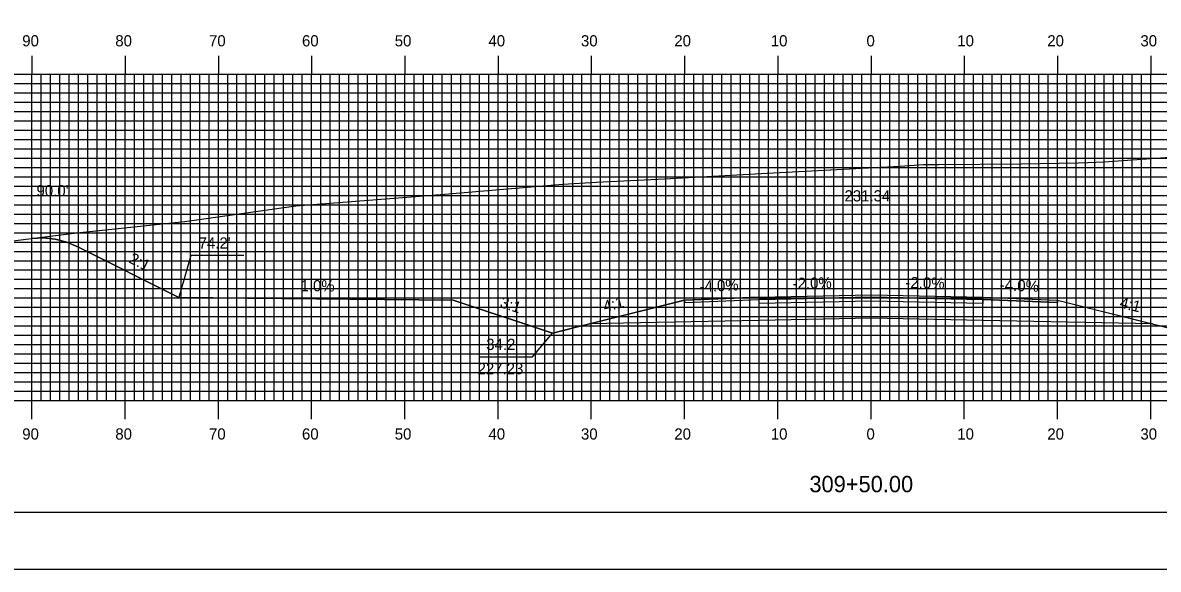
# Model space of a CAD drawing. Extents: x 1818063 to 1818407, y 442591 to 442811.
# Drawn here: x 1818138.1 to 1818259.9, y 442590.5 to 442649.2 of the extents above; entities that cross this region are included whole.
import ezdxf

# ---------------------------------------------------------------- set-up
doc = ezdxf.new("R2010")
doc.units = 0
for name, color, linetype in [('ANNOTATION', 7, 'Continuous'), ('BORDER', 7, 'Continuous'), ('D_Roadway_Centerline', 7, 'Continuous'), ('D_Roadway_Centerline_Text', 7, 'Continuous'), ('D_Roadway_Edge_Shoulder', 7, 'Continuous'), ('D_Roadway_Edge_TW', 7, 'Continuous'), ('D_Roadway_Pavement', 7, 'Continuous'), ('D_Roadway_SlopeLines', 7, 'Continuous'), ('D_Roadway_SubGrade', 7, 'Continuous'), ('D_Text_Standard', 7, 'Continuous'), ('H_V ANNOTATION', 7, 'Continuous'), ('MAJOR', 7, 'Continuous'), ('MINOR', 7, 'Continuous'), ('PLOT BOUNDARY', 7, 'Continuous'), ('S_Roadway_Centerline', 7, 'Continuous')]:
    doc.layers.add(name, color=color, linetype=linetype)

msp = doc.modelspace()

# ---------------------------------------------------------------- linework, layer by layer
at = {"layer": 'ANNOTATION'}
for points in [[(1818161.87, 442624.24), (1818156.18, 442624.24), (1818154.91, 442619.73)], [(1818187.13, 442613.36), (1818192.82, 442613.36), (1818194.95, 442615.9)]]:
    msp.add_lwpolyline(points, dxfattribs=at)
at = {"layer": 'BORDER'}
msp.add_lwpolyline([(1818079.53, 442596.67), (1818399.53, 442596.67), (1818399.53, 442806.67), (1818079.53, 442806.67)], close=True, dxfattribs=at)
at = {"layer": 'D_Roadway_Centerline'}
msp.add_lwpolyline([(1818139.13, 442626.06), (1818140.38, 442626.12), (1818141.63, 442625.99), (1818142.88, 442625.65), (1818144.13, 442625.13), (1818154.91, 442619.73), (1818184.32, 442619.44), (1818194.95, 442615.9), (1818198.95, 442616.9), (1818209.13, 442619.44), (1818217.13, 442619.76), (1818229.13, 442620), (1818241.13, 442619.76), (1818249.13, 442619.44), (1818259.3, 442616.9), (1818263.3, 442615.9), (1818273.93, 442619.44), (1818281.06, 442619.51), (1818314.13, 442636.04), (1818315.38, 442636.59), (1818316.63, 442637), (1818317.88, 442637.25), (1818319.13, 442637.35)], dxfattribs=at)
at = {"layer": 'D_Roadway_Edge_Shoulder'}
for points in [[(1818217.13, 442619.76), (1818209.13, 442619.44), (1818209.13, 442619.19), (1818217.13, 442619.51)], [(1818241.13, 442619.76), (1818249.13, 442619.44), (1818249.13, 442619.19), (1818241.13, 442619.51)]]:
    msp.add_lwpolyline(points, close=True, dxfattribs=at)
at = {"layer": 'D_Roadway_Edge_TW'}
msp.add_lwpolyline([(1818217.13, 442619.51), (1818217.13, 442619.76), (1818229.13, 442620), (1818241.13, 442619.76), (1818241.13, 442619.51), (1818229.13, 442619.75)], close=True, dxfattribs=at)
at = {"layer": 'D_Roadway_Pavement'}
msp.add_lwpolyline([(1818217.13, 442619.09), (1818217.13, 442619.51), (1818229.13, 442619.75), (1818241.13, 442619.51), (1818241.13, 442619.09), (1818229.13, 442619.33)], close=True, dxfattribs=at)
at = {"layer": 'D_Roadway_SlopeLines'}
for points in [[(1818184.32, 442619.44), (1818154.91, 442619.73), (1818144.13, 442625.13), (1818142.88, 442625.65), (1818141.63, 442625.99), (1818140.38, 442626.12), (1818139.13, 442626.06)], [(1818194.95, 442615.9), (1818184.32, 442619.44)], [(1818209.13, 442619.44), (1818194.95, 442615.9)], [(1818249.13, 442619.44), (1818263.3, 442615.9)]]:
    msp.add_lwpolyline(points, dxfattribs=at)
at = {"layer": 'D_Roadway_SubGrade'}
msp.add_lwpolyline([(1818217.13, 442617.26), (1818198.95, 442616.9), (1818209.13, 442619.44), (1818209.13, 442619.19), (1818217.13, 442619.51), (1818229.13, 442619.75), (1818241.13, 442619.51), (1818249.13, 442619.19), (1818249.13, 442619.44), (1818259.3, 442616.9), (1818241.13, 442617.26), (1818229.13, 442617.5)], close=True, dxfattribs=at)
at = {"layer": 'MAJOR'}
for p, q in [((1818139.13, 442645.67), (1818139.13, 442643.67)), ((1818149.13, 442645.67), (1818149.13, 442643.67)), ((1818159.13, 442645.67), (1818159.13, 442643.67)), ((1818169.13, 442645.67), (1818169.13, 442643.67)), ((1818179.13, 442645.67), (1818179.13, 442643.67)), ((1818189.13, 442645.67), (1818189.13, 442643.67)), ((1818199.13, 442645.67), (1818199.13, 442643.67)), ((1818209.13, 442645.67), (1818209.13, 442643.67)), ((1818219.13, 442645.67), (1818219.13, 442643.67)), ((1818229.13, 442645.67), (1818229.13, 442643.67)), ((1818239.13, 442645.67), (1818239.13, 442643.67)), ((1818249.13, 442645.67), (1818249.13, 442643.67)), ((1818259.13, 442645.67), (1818259.13, 442643.67)), ((1818089.13, 442643.67), (1818369.13, 442643.67)), ((1818089.13, 442643.67), (1818369.13, 442643.67)), ((1818139.13, 442608.67), (1818139.13, 442643.67)), ((1818149.13, 442608.67), (1818149.13, 442643.67)), ((1818159.13, 442608.67), (1818159.13, 442643.67)), ((1818169.13, 442608.67), (1818169.13, 442643.67)), ((1818179.13, 442608.67), (1818179.13, 442643.67)), ((1818189.13, 442608.67), (1818189.13, 442643.67)), ((1818199.13, 442608.67), (1818199.13, 442643.67)), ((1818209.13, 442608.67), (1818209.13, 442643.67)), ((1818219.13, 442608.67), (1818219.13, 442643.67)), ((1818229.13, 442608.67), (1818229.13, 442643.67)), ((1818239.13, 442608.67), (1818239.13, 442643.67)), ((1818249.13, 442608.67), (1818249.13, 442643.67)), ((1818259.13, 442608.67), (1818259.13, 442643.67)), ((1818089.13, 442638.67), (1818369.13, 442638.67)), ((1818089.13, 442633.67), (1818369.13, 442633.67)), ((1818089.13, 442628.67), (1818369.13, 442628.67)), ((1818089.13, 442623.67), (1818369.13, 442623.67)), ((1818089.13, 442618.67), (1818369.13, 442618.67)), ((1818089.13, 442613.67), (1818369.13, 442613.67)), ((1818089.13, 442608.67), (1818369.13, 442608.67)), ((1818089.13, 442608.67), (1818369.13, 442608.67)), ((1818139.13, 442606.66), (1818139.13, 442608.67)), ((1818149.13, 442606.66), (1818149.13, 442608.67)), ((1818159.13, 442606.66), (1818159.13, 442608.67)), ((1818169.13, 442606.66), (1818169.13, 442608.67)), ((1818179.13, 442606.66), (1818179.13, 442608.67)), ((1818189.13, 442606.66), (1818189.13, 442608.67)), ((1818199.13, 442606.66), (1818199.13, 442608.67)), ((1818209.13, 442606.66), (1818209.13, 442608.67)), ((1818219.13, 442606.66), (1818219.13, 442608.67)), ((1818229.13, 442606.66), (1818229.13, 442608.67)), ((1818239.13, 442606.66), (1818239.13, 442608.67)), ((1818249.13, 442606.66), (1818249.13, 442608.67)), ((1818259.13, 442606.66), (1818259.13, 442608.67))]:
    msp.add_line(p, q, dxfattribs=at)
at = {"layer": 'MINOR'}
for p, q in [((1818140.13, 442608.67), (1818140.13, 442643.67)), ((1818141.13, 442608.67), (1818141.13, 442643.67)), ((1818142.13, 442608.67), (1818142.13, 442643.67)), ((1818143.13, 442608.67), (1818143.13, 442643.67)), ((1818144.13, 442608.67), (1818144.13, 442643.67)), ((1818145.13, 442608.67), (1818145.13, 442643.67)), ((1818146.13, 442608.67), (1818146.13, 442643.67)), ((1818147.13, 442608.67), (1818147.13, 442643.67)), ((1818148.13, 442608.67), (1818148.13, 442643.67)), ((1818150.13, 442608.67), (1818150.13, 442643.67)), ((1818151.13, 442608.67), (1818151.13, 442643.67)), ((1818152.13, 442608.67), (1818152.13, 442643.67)), ((1818153.13, 442608.67), (1818153.13, 442643.67)), ((1818154.13, 442608.67), (1818154.13, 442643.67)), ((1818155.13, 442608.67), (1818155.13, 442643.67)), ((1818156.13, 442608.67), (1818156.13, 442643.67)), ((1818157.13, 442608.67), (1818157.13, 442643.67)), ((1818158.13, 442608.67), (1818158.13, 442643.67)), ((1818160.13, 442608.67), (1818160.13, 442643.67)), ((1818161.13, 442608.67), (1818161.13, 442643.67)), ((1818162.13, 442608.67), (1818162.13, 442643.67)), ((1818163.13, 442608.67), (1818163.13, 442643.67)), ((1818164.13, 442608.67), (1818164.13, 442643.67)), ((1818165.13, 442608.67), (1818165.13, 442643.67)), ((1818166.13, 442608.67), (1818166.13, 442643.67)), ((1818167.13, 442608.67), (1818167.13, 442643.67)), ((1818168.13, 442608.67), (1818168.13, 442643.67)), ((1818170.13, 442608.67), (1818170.13, 442643.67)), ((1818171.13, 442608.67), (1818171.13, 442643.67)), ((1818172.13, 442608.67), (1818172.13, 442643.67)), ((1818173.13, 442608.67), (1818173.13, 442643.67)), ((1818174.13, 442608.67), (1818174.13, 442643.67)), ((1818175.13, 442608.67), (1818175.13, 442643.67)), ((1818176.13, 442608.67), (1818176.13, 442643.67)), ((1818177.13, 442608.67), (1818177.13, 442643.67)), ((1818178.13, 442608.67), (1818178.13, 442643.67)), ((1818180.13, 442608.67), (1818180.13, 442643.67)), ((1818181.13, 442608.67), (1818181.13, 442643.67)), ((1818182.13, 442608.67), (1818182.13, 442643.67)), ((1818183.13, 442608.67), (1818183.13, 442643.67)), ((1818184.13, 442608.67), (1818184.13, 442643.67)), ((1818185.13, 442608.67), (1818185.13, 442643.67)), ((1818186.13, 442608.67), (1818186.13, 442643.67)), ((1818187.13, 442608.67), (1818187.13, 442643.67)), ((1818188.13, 442608.67), (1818188.13, 442643.67)), ((1818190.13, 442608.67), (1818190.13, 442643.67)), ((1818191.13, 442608.67), (1818191.13, 442643.67)), ((1818192.13, 442608.67), (1818192.13, 442643.67)), ((1818193.13, 442608.67), (1818193.13, 442643.67)), ((1818194.13, 442608.67), (1818194.13, 442643.67)), ((1818195.13, 442608.67), (1818195.13, 442643.67)), ((1818196.13, 442608.67), (1818196.13, 442643.67)), ((1818197.13, 442608.67), (1818197.13, 442643.67)), ((1818198.13, 442608.67), (1818198.13, 442643.67)), ((1818200.13, 442608.67), (1818200.13, 442643.67)), ((1818201.13, 442608.67), (1818201.13, 442643.67)), ((1818202.13, 442608.67), (1818202.13, 442643.67)), ((1818203.13, 442608.67), (1818203.13, 442643.67)), ((1818204.13, 442608.67), (1818204.13, 442643.67)), ((1818205.13, 442608.67), (1818205.13, 442643.67)), ((1818206.13, 442608.67), (1818206.13, 442643.67)), ((1818207.13, 442608.67), (1818207.13, 442643.67)), ((1818208.13, 442608.67), (1818208.13, 442643.67)), ((1818210.13, 442608.67), (1818210.13, 442643.67)), ((1818211.13, 442608.67), (1818211.13, 442643.67)), ((1818212.13, 442608.67), (1818212.13, 442643.67)), ((1818213.13, 442608.67), (1818213.13, 442643.67)), ((1818214.13, 442608.67), (1818214.13, 442643.67)), ((1818215.13, 442608.67), (1818215.13, 442643.67)), ((1818216.13, 442608.67), (1818216.13, 442643.67)), ((1818217.13, 442608.67), (1818217.13, 442643.67)), ((1818218.13, 442608.67), (1818218.13, 442643.67)), ((1818220.13, 442608.67), (1818220.13, 442643.67)), ((1818221.13, 442608.67), (1818221.13, 442643.67)), ((1818222.13, 442608.67), (1818222.13, 442643.67)), ((1818223.13, 442608.67), (1818223.13, 442643.67)), ((1818224.13, 442608.67), (1818224.13, 442643.67)), ((1818225.13, 442608.67), (1818225.13, 442643.67)), ((1818226.13, 442608.67), (1818226.13, 442643.67)), ((1818227.13, 442608.67), (1818227.13, 442643.67)), ((1818228.13, 442608.67), (1818228.13, 442643.67)), ((1818230.13, 442608.67), (1818230.13, 442643.67)), ((1818231.13, 442608.67), (1818231.13, 442643.67)), ((1818232.13, 442608.67), (1818232.13, 442643.67)), ((1818233.13, 442608.67), (1818233.13, 442643.67)), ((1818234.13, 442608.67), (1818234.13, 442643.67)), ((1818235.13, 442608.67), (1818235.13, 442643.67)), ((1818236.13, 442608.67), (1818236.13, 442643.67)), ((1818237.13, 442608.67), (1818237.13, 442643.67)), ((1818238.13, 442608.67), (1818238.13, 442643.67)), ((1818240.13, 442608.67), (1818240.13, 442643.67)), ((1818241.13, 442608.67), (1818241.13, 442643.67)), ((1818242.13, 442608.67), (1818242.13, 442643.67)), ((1818243.13, 442608.67), (1818243.13, 442643.67)), ((1818244.13, 442608.67), (1818244.13, 442643.67)), ((1818245.13, 442608.67), (1818245.13, 442643.67)), ((1818246.13, 442608.67), (1818246.13, 442643.67)), ((1818247.13, 442608.67), (1818247.13, 442643.67)), ((1818248.13, 442608.67), (1818248.13, 442643.67)), ((1818250.13, 442608.67), (1818250.13, 442643.67)), ((1818251.13, 442608.67), (1818251.13, 442643.67)), ((1818252.13, 442608.67), (1818252.13, 442643.67)), ((1818253.13, 442608.67), (1818253.13, 442643.67)), ((1818254.13, 442608.67), (1818254.13, 442643.67)), ((1818255.13, 442608.67), (1818255.13, 442643.67)), ((1818256.13, 442608.67), (1818256.13, 442643.67)), ((1818257.13, 442608.67), (1818257.13, 442643.67)), ((1818258.13, 442608.67), (1818258.13, 442643.67)), ((1818089.13, 442642.67), (1818369.13, 442642.67)), ((1818089.13, 442641.67), (1818369.13, 442641.67)), ((1818089.13, 442640.67), (1818369.13, 442640.67)), ((1818089.13, 442639.67), (1818369.13, 442639.67)), ((1818089.13, 442637.67), (1818369.13, 442637.67)), ((1818089.13, 442636.67), (1818369.13, 442636.67)), ((1818089.13, 442635.67), (1818369.13, 442635.67)), ((1818089.13, 442634.67), (1818369.13, 442634.67)), ((1818089.13, 442632.67), (1818369.13, 442632.67)), ((1818089.13, 442631.67), (1818369.13, 442631.67)), ((1818089.13, 442630.67), (1818369.13, 442630.67)), ((1818089.13, 442629.67), (1818369.13, 442629.67)), ((1818089.13, 442627.67), (1818369.13, 442627.67)), ((1818089.13, 442626.67), (1818369.13, 442626.67)), ((1818089.13, 442625.67), (1818369.13, 442625.67)), ((1818089.13, 442624.67), (1818369.13, 442624.67)), ((1818089.13, 442622.67), (1818369.13, 442622.67)), ((1818089.13, 442621.67), (1818369.13, 442621.67)), ((1818089.13, 442620.67), (1818369.13, 442620.67)), ((1818089.13, 442619.67), (1818369.13, 442619.67)), ((1818089.13, 442617.67), (1818369.13, 442617.67)), ((1818089.13, 442616.67), (1818369.13, 442616.67)), ((1818089.13, 442615.67), (1818369.13, 442615.67)), ((1818089.13, 442614.67), (1818369.13, 442614.67)), ((1818089.13, 442612.67), (1818369.13, 442612.67)), ((1818089.13, 442611.67), (1818369.13, 442611.67)), ((1818089.13, 442610.67), (1818369.13, 442610.67)), ((1818089.13, 442609.67), (1818369.13, 442609.67))]:
    msp.add_line(p, q, dxfattribs=at)
at = {"layer": 'PLOT BOUNDARY'}
msp.add_lwpolyline([(1818063.34, 442590.55), (1818403.34, 442590.55), (1818403.34, 442810.55), (1818063.34, 442810.55)], close=True, dxfattribs=at)
at = {"layer": 'S_Roadway_Centerline'}
msp.add_lwpolyline([(1818089.13, 442619.38), (1818099.38, 442621.1), (1818113.86, 442622.94), (1818115.04, 442623.07), (1818116.47, 442623.23), (1818143.95, 442626.67), (1818155.52, 442627.86), (1818167.43, 442629.55), (1818182.08, 442630.7), (1818182.46, 442630.73), (1818182.54, 442630.74), (1818196.08, 442631.87), (1818199.69, 442632.1), (1818206.98, 442632.46), (1818218, 442633.06), (1818232.25, 442633.81), (1818234.77, 442633.98), (1818236.39, 442633.98), (1818245.22, 442634.08), (1818251.33, 442634.17), (1818252.39, 442634.21), (1818254.12, 442634.29), (1818267.71, 442635.24)], dxfattribs=at)

# ---------------------------------------------------------------- texts
at = {"layer": 'ANNOTATION'}
for s, p in [("74.2'", (1818157.02, 442624.97)), ("34.2'", (1818187.86, 442614.09)), ('227.23', (1818186.93, 442611.49))]:
    msp.add_text(s, height=1.2, dxfattribs=at).set_placement(p)
for s, rotation, p in [('2:1', 333.4349, (1818149.45, 442623.5)), ('1.0%', 359.4271, (1818167.94, 442620.4)), ('-4.0%', 2.2906, (1818210.76, 442620.31)), ('-2.0%', 1.1458, (1818220.73, 442620.63)), ('-2.0%', 358.8542, (1818232.81, 442620.73)), ('-4.0%', 357.7094, (1818242.92, 442620.49)), ('3:1', 341.5652, (1818189.24, 442618.71)), ('4:1', 14.0362, (1818200.57, 442618.16)), ('4:1', 345.9638, (1818255.72, 442618.65))]:
    msp.add_text(s, height=1.2, rotation=rotation, dxfattribs=at).set_placement(p)
at = {"layer": 'D_Roadway_Centerline'}
for s, p in [('C', (1818229.12, 442620)), ('L', (1818229.13, 442619.99))]:
    msp.add_text(s, height=0.0146, dxfattribs=at).set_placement(p)
at = {"layer": 'D_Roadway_Centerline_Text'}
msp.add_text('231.34', height=1.2, dxfattribs=at).set_placement((1818226.28, 442630.03))
at = {"layer": 'D_Text_Standard'}
msp.add_text("90.0'", height=1.2, dxfattribs=at).set_placement((1818139.63, 442630.58))
at = {"layer": 'H_V ANNOTATION'}
for s, height, p in [('90', 1.2, (1818138.1, 442646.67)), ('80', 1.2, (1818148.08, 442646.67)), ('70', 1.2, (1818158.13, 442646.67)), ('60', 1.2, (1818168.1, 442646.67)), ('50', 1.2, (1818178.05, 442646.67)), ('40', 1.2, (1818188.1, 442646.67)), ('30', 1.2, (1818198.02, 442646.67)), ('20', 1.2, (1818208.03, 442646.67)), ('10', 1.2, (1818218.38, 442646.67)), ('0', 1.2, (1818228.64, 442646.67)), ('10', 1.2, (1818238.38, 442646.67)), ('20', 1.2, (1818248.03, 442646.67)), ('30', 1.2, (1818258.02, 442646.67)), ('90', 1.2, (1818138.1, 442604.47)), ('80', 1.2, (1818148.08, 442604.47)), ('70', 1.2, (1818158.13, 442604.47)), ('60', 1.2, (1818168.1, 442604.47)), ('50', 1.2, (1818178.05, 442604.47)), ('40', 1.2, (1818188.1, 442604.47)), ('30', 1.2, (1818198.02, 442604.47)), ('20', 1.2, (1818208.03, 442604.47)), ('10', 1.2, (1818218.38, 442604.47)), ('0', 1.2, (1818228.64, 442604.47)), ('10', 1.2, (1818238.38, 442604.47)), ('20', 1.2, (1818248.03, 442604.47)), ('30', 1.2, (1818258.02, 442604.47)), ('309+50.00', 1.75, (1818222.52, 442598.82))]:
    msp.add_text(s, height=height, dxfattribs=at).set_placement(p)

doc.saveas('drawing.dxf')
